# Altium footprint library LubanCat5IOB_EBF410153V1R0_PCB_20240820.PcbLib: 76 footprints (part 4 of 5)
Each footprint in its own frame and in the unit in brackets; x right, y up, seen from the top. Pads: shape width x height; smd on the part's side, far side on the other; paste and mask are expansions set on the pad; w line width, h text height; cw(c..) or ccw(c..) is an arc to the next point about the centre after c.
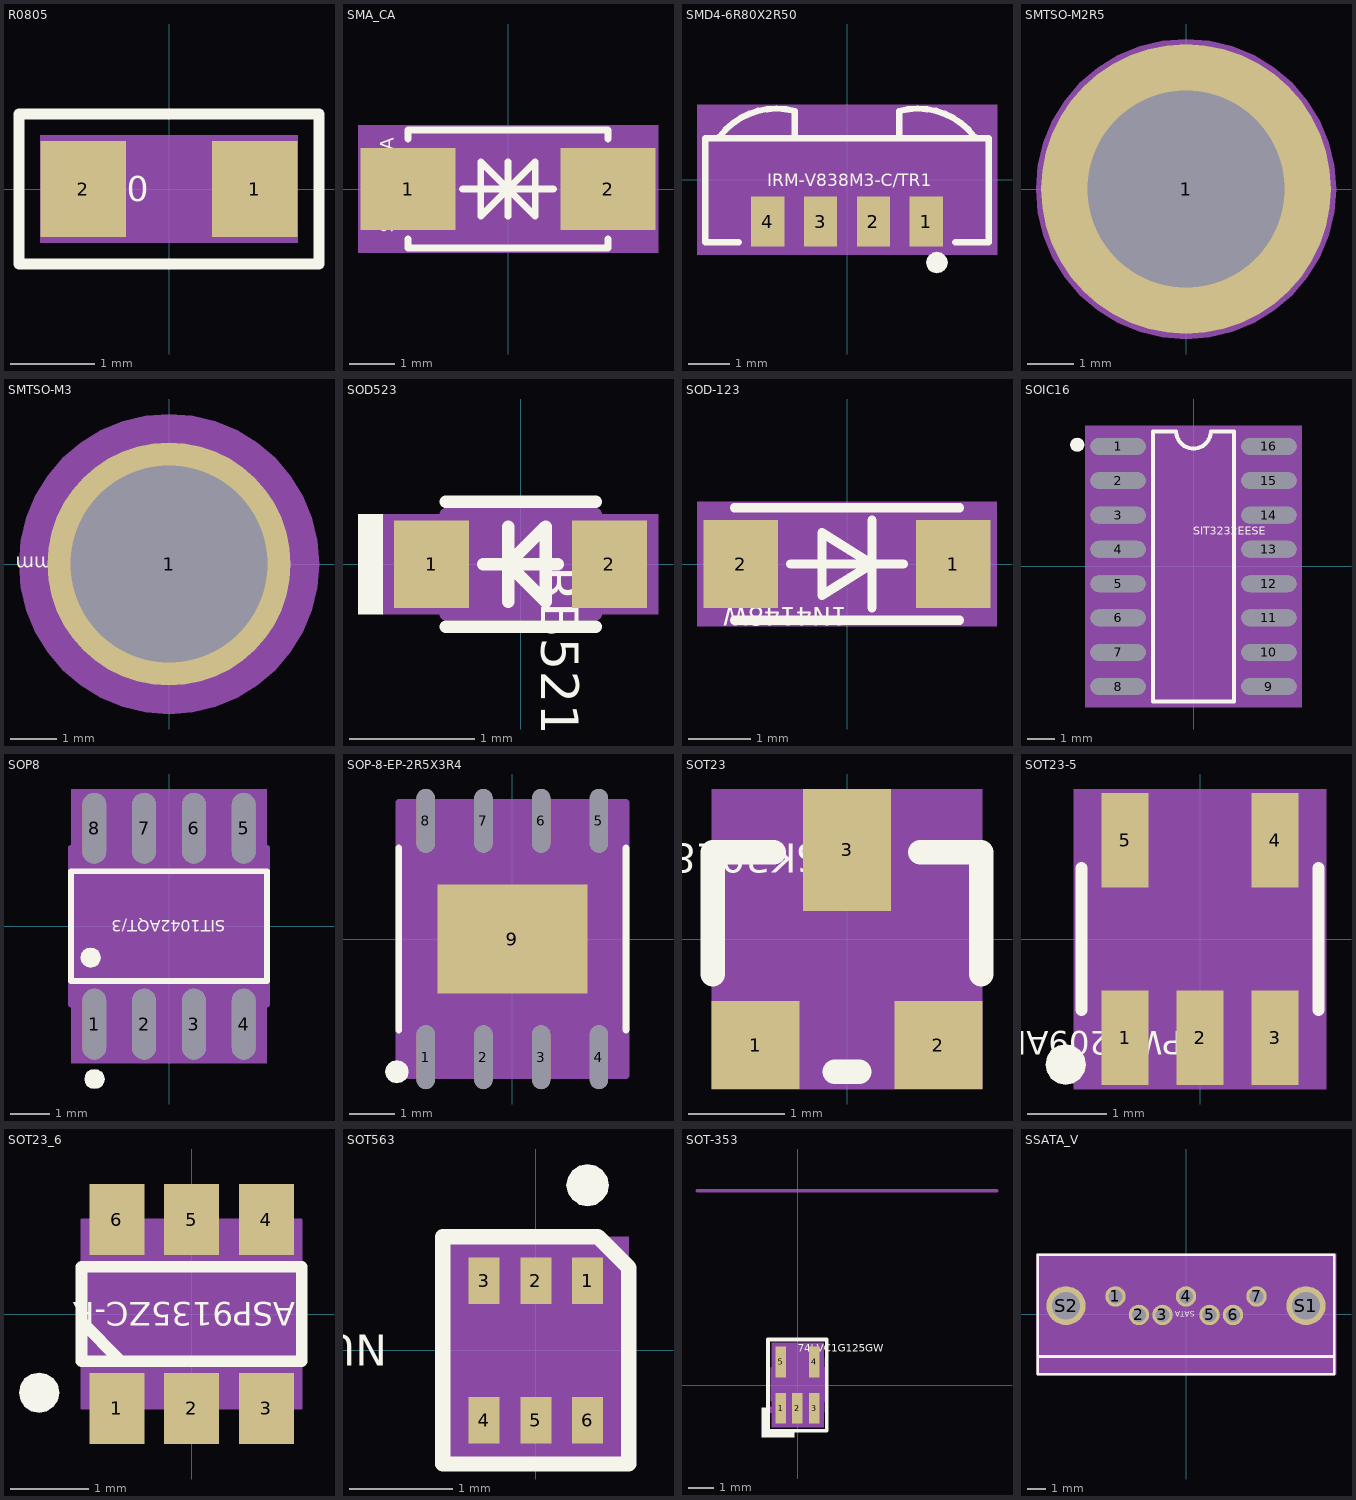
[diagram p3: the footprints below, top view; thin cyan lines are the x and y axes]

## R0805 [mil] "R0805"
pads (2):
  rect 40x45 smd: 1(40,0) 2(-40,0)
Top Overlay:
  lines w5: -70,-35 70,-35 70,35 -70,35 -70,-35
  text "0R" at -9.45,5.91 h11.81
Top 3D Body:
  region: 60,-25 -60,-25 -60,25 60,25
Mechanical 15:
  text "2" at -52,0 h30
  text "1" at 28,0 h30
3D body: height 150, standoff 0, extent -60,-25 60,25

## SMA_CA [mm] "SMA_CA"
pads (2):
  rect 2.1x1.8 smd: 1(-2.2,0) 2(2.2,0)
Top Overlay:
  lines w0.15: -2.2,-1.1 -2.2,-1.3 2.2,-1.3 2.2,-1.1 ; -2.2,1.1 -2.2,1.3 2.2,1.3 2.2,1.1 ; -1,0 1,0 ; 0,-0.6 0,0.6 ; 0,0 -0.6,-0.6 -0.6,0.6 0,0 ; 0,0 0.6,0.6 0.6,-0.6 0,0
  text "SMAJ13CA" at -2.517,-0.96 h0.3
Top 3D Body:
  region: -3.3,1.4 -3.3,-1.4 3.3,-1.4 3.3,1.4
Mechanical 15:
  text "2" at 2.2,-0.254 h0.64
  text "1" at -2.2,-0.254 h0.64
Top Assembly:
  lines w0.15: -2.2,-1.25 2.2,-1.25 2.2,1.25 -2.2,1.25 -2.2,-1.25
3D body: height 3.81, standoff 0, extent -3.3,-1.4 3.3,1.4

## SMD4-6R80X2R50 [mm] "SMD4-6R80X2R50"
pads (4):
  rect 0.8x1.2 smd: 1(1.905,-1) 2(0.635,-1) 3(-0.635,-1) 4(-1.905,-1)
Top Overlay:
  dashed: 2.414,-1.985 2.395,-1.887 2.339,-1.805 2.257,-1.75 2.159,-1.73 2.061,-1.75 2.034,-1.768 1.979,-1.805 1.923,-1.887 1.904,-1.985 1.923,-2.083 1.979,-2.165 2.034,-2.202 2.061,-2.221 2.159,-2.24 2.257,-2.221 2.339,-2.165 2.395,-2.083
  lines w0.15: -2.6,-1.5 -3.4,-1.5 -3.4,1 3.4,1 3.4,-1.5 2.6,-1.5
  lines w0.152: -3.053,1.041 cw(c-1.7,0.011) -1.25,1.651 -1.25,1 ; 1.25,1 1.25,1.651 cw(c1.7,0.012) 3.053,1.041
  text "IRM-V838M3-C/TR1" at -1.92,-0.15 h0.3
Top 3D Body:
  region: -3.6,1.8 -3.6,-1.8 3.6,-1.8 3.6,1.8
Mechanical 15:
  text "3" at -0.889,-1 h0.64
  text "1" at 1.651,-1 h0.64
  text "4" at -2.159,-1 h0.64
  text "2" at 0.381,-1 h0.64
Top Assembly:
  lines w0.15: -3.4,-1.5 3.4,-1.5 3.4,1 -3.4,1 -3.4,-1.5
3D body: height 3.81, standoff 0, extent -3.6,-1.8 3.6,1.8

## SMTSO-M2R5 [mm] "SMTSO-M2R5"
pads (1):
  round 6.2 / inner round 5.2 / far side round 5.2 hole 4.22: 1(0,0)
Top Overlay:
  text "M2.5X1.5mm" at -1.2,-0.15 h0.3
Top Paste:
  dashed: -0.4,3.074 -0.4,2.072 -0.579,2.029 -0.754,1.971 -0.923,1.898 -1.084,1.81 -1.238,1.709 -1.382,1.594 -1.516,1.468 -1.638,1.33 -1.748,1.182 -1.844,1.025 -1.926,0.861 -1.994,0.689 -2.047,0.513 -2.072,0.4 -3.074,0.4 -3.028,0.666 -2.958,0.928 -2.866,1.182 -2.752,1.427 -2.617,1.662 -2.462,1.883 -2.289,2.091 -2.098,2.282 -1.891,2.457 -1.67,2.612 -1.436,2.748 -1.191,2.862 -0.937,2.955 -0.676,3.026 -0.409,3.073
  dashed: -3.074,-0.4 -2.072,-0.4 -2.029,-0.579 -1.971,-0.754 -1.898,-0.923 -1.81,-1.084 -1.709,-1.238 -1.594,-1.382 -1.468,-1.516 -1.33,-1.638 -1.182,-1.748 -1.025,-1.844 -0.861,-1.926 -0.689,-1.994 -0.513,-2.047 -0.4,-2.072 -0.4,-3.074 -0.666,-3.028 -0.928,-2.958 -1.182,-2.866 -1.427,-2.752 -1.662,-2.617 -1.883,-2.462 -2.091,-2.289 -2.282,-2.098 -2.457,-1.891 -2.612,-1.67 -2.748,-1.436 -2.862,-1.191 -2.955,-0.937 -3.026,-0.676 -3.073,-0.409
  dashed: 0.4,-3.074 0.4,-2.072 0.579,-2.029 0.754,-1.971 0.923,-1.898 1.084,-1.81 1.238,-1.709 1.382,-1.594 1.516,-1.468 1.638,-1.33 1.748,-1.182 1.844,-1.025 1.926,-0.861 1.994,-0.689 2.047,-0.513 2.072,-0.4 3.074,-0.4 3.028,-0.666 2.958,-0.928 2.866,-1.182 2.752,-1.427 2.617,-1.662 2.462,-1.883 2.289,-2.091 2.098,-2.282 1.891,-2.457 1.67,-2.612 1.436,-2.748 1.191,-2.862 0.937,-2.955 0.676,-3.026 0.409,-3.073
  dashed: 3.074,0.4 2.072,0.4 2.029,0.579 1.971,0.754 1.898,0.923 1.81,1.084 1.709,1.238 1.594,1.382 1.468,1.516 1.33,1.638 1.182,1.748 1.025,1.844 0.861,1.926 0.689,1.994 0.513,2.047 0.4,2.072 0.4,3.074 0.666,3.028 0.928,2.958 1.182,2.866 1.427,2.752 1.662,2.617 1.883,2.462 2.091,2.289 2.282,2.098 2.457,1.891 2.612,1.67 2.748,1.436 2.862,1.191 2.955,0.937 3.026,0.676 3.073,0.409
Top 3D Body:
  region: 3.21,0 3.17,0.502 3.053,0.992 2.86,1.457 2.597,1.887 2.27,2.27 1.887,2.597 1.457,2.86 0.992,3.053 0.502,3.17 0,3.21 -0.502,3.17 -0.992,3.053 -1.457,2.86 -1.601,2.772 -1.887,2.597 -2.27,2.27 -2.597,1.887 -2.86,1.457 -3.053,0.992 -3.17,0.502 -3.21,0 -3.17,-0.502 -3.053,-0.992 -2.86,-1.457 -2.597,-1.887 -2.27,-2.27 -1.887,-2.597 -1.601,-2.772 -1.457,-2.86 -0.992,-3.053 -0.502,-3.17 0,-3.21 0.502,-3.17 0.992,-3.053 1.457,-2.86 1.887,-2.597 2.27,-2.27 2.597,-1.887 2.86,-1.457 3.053,-0.992 3.17,-0.502
Mechanical 15:
  text "1" at -0.254,0 h0.64
Top Assembly:
  circle w0.025: c0,0 r3.1
3D body: height 3.81, standoff 0, extent -3.21,-3.21 3.21,3.21

## SMTSO-M3 [mm] "SMTSO-M3"
pads (1):
  round 5.2 / inner round 5.2 / far side round 6.2 hole 4.22: 1(0,0)
Top Overlay:
  text "M3X3.5mm" at -0.96,0.15 h0.3
Top Paste:
  dashed: 3.074,-0.4 3.028,-0.666 2.958,-0.928 2.866,-1.182 2.752,-1.427 2.617,-1.662 2.462,-1.883 2.289,-2.091 2.098,-2.282 1.891,-2.457 1.67,-2.612 1.436,-2.748 1.191,-2.862 0.937,-2.955 0.676,-3.026 0.409,-3.073 0.4,-3.074 0.4,-2.062 0.578,-2.019 0.752,-1.961 0.92,-1.888 1.081,-1.8 1.234,-1.699 1.377,-1.585 1.51,-1.459 1.632,-1.322 1.741,-1.175 1.836,-1.019 1.918,-0.855 1.985,-0.684 2.037,-0.509 2.062,-0.4
  dashed: 0.4,3.074 0.666,3.028 0.928,2.958 1.182,2.866 1.427,2.752 1.662,2.617 1.883,2.462 2.091,2.289 2.282,2.098 2.457,1.891 2.612,1.67 2.748,1.436 2.862,1.191 2.955,0.937 3.026,0.676 3.073,0.409 3.074,0.4 2.062,0.4 2.019,0.578 1.961,0.752 1.888,0.92 1.8,1.081 1.699,1.234 1.585,1.377 1.459,1.51 1.322,1.632 1.175,1.741 1.019,1.836 0.855,1.918 0.684,1.985 0.509,2.037 0.4,2.062
  dashed: -3.074,0.4 -3.028,0.666 -2.958,0.928 -2.866,1.182 -2.752,1.427 -2.617,1.662 -2.462,1.883 -2.289,2.091 -2.098,2.282 -1.891,2.457 -1.67,2.612 -1.436,2.748 -1.191,2.862 -0.937,2.955 -0.676,3.026 -0.409,3.073 -0.4,3.074 -0.4,2.062 -0.578,2.019 -0.752,1.961 -0.92,1.888 -1.081,1.8 -1.234,1.699 -1.377,1.585 -1.51,1.459 -1.632,1.322 -1.741,1.175 -1.836,1.019 -1.918,0.855 -1.985,0.684 -2.037,0.509 -2.062,0.4
  dashed: -0.4,-3.074 -0.666,-3.028 -0.928,-2.958 -1.182,-2.866 -1.427,-2.752 -1.662,-2.617 -1.883,-2.462 -2.091,-2.289 -2.282,-2.098 -2.457,-1.891 -2.612,-1.67 -2.748,-1.436 -2.862,-1.191 -2.955,-0.937 -3.026,-0.676 -3.073,-0.409 -3.074,-0.4 -2.062,-0.4 -2.019,-0.578 -1.961,-0.752 -1.888,-0.92 -1.8,-1.081 -1.699,-1.234 -1.585,-1.377 -1.459,-1.51 -1.322,-1.632 -1.175,-1.741 -1.019,-1.836 -0.855,-1.918 -0.684,-1.985 -0.509,-2.037 -0.4,-2.062
Top 3D Body:
  region: 3.21,0 3.17,-0.502 3.053,-0.992 2.86,-1.457 2.597,-1.887 2.27,-2.27 1.887,-2.597 1.457,-2.86 0.992,-3.053 0.502,-3.17 0,-3.21 -0.502,-3.17 -0.992,-3.053 -1.457,-2.86 -1.601,-2.772 -1.887,-2.597 -2.27,-2.27 -2.597,-1.887 -2.86,-1.457 -3.053,-0.992 -3.17,-0.502 -3.21,0 -3.17,0.502 -3.053,0.992 -2.86,1.457 -2.597,1.887 -2.27,2.27 -1.887,2.597 -1.601,2.772 -1.457,2.86 -0.992,3.053 -0.502,3.17 0,3.21 0.502,3.17 0.992,3.053 1.457,2.86 1.887,2.597 2.27,2.27 2.597,1.887 2.86,1.457 3.053,0.992 3.17,0.502
Mechanical 15:
  text "1" at -0.376,0 h0.94
Top Assembly:
  circle w0.025: c0,0 r3.1
3D body: height 3.81, standoff 0, extent -3.21,-3.21 3.21,3.21

## SOD523 [mm] "SOD523"
pads (2):
  rect 0.6x0.7 smd: 1(-0.71,0) 2(0.71,0)
Top Overlay:
  dashed: -1.3,0.4 -1.3,-0.4 -1.1,-0.4 -1.1,0.4
  lines w0.1: -0.6,-0.5 0.6,-0.5 ; -0.6,0.5 0.6,0.5 ; -0.3,0 0.3,0 ; -0.1,-0.3 -0.1,0.3 ; -0.1,0 0.2,0.3 0.2,-0.3 -0.1,0
  text "RB521S-30" at 0.167,-0.016 h0.3
Top 3D Body:
  region: -1.1,0.4 -1.1,-0.4 1.1,-0.4 1.1,0.4
Mechanical 15:
  text "2" at 0.456,0 h0.64
  text "1" at -0.964,0 h0.64
Top Assembly:
  lines w0.1: -0.6,-0.4 0.6,-0.4 0.6,0.4 -0.6,0.4 -0.6,-0.4
3D body: height 3.81, standoff 0, extent -1.1,-0.4 1.1,0.4

## SOD-123 [mm] "SOD-123"
pads (2):
  rect 1.2x1.4 smd: 1(1.7,0) 2(-1.7,0)
Top Overlay:
  lines w0.15: -1.8,-0.9 1.8,-0.9 ; -1.8,0.9 1.8,0.9 ; -0.9,0 0.9,0 ; 0.4,-0.7 0.4,0.7 ; -0.4,-0.5 -0.4,0.5 0.4,0 -0.4,-0.5
  text "1N4148W" at 0,-0.69 h0.3
Top 3D Body:
  region: -2.4,-1 2.4,-1 2.4,1 -2.4,1
Mechanical 15:
  text "2" at -1.7,-0.315 h0.79
  text "1" at 1.7,-0.315 h0.79
Top Assembly:
  lines w0.15: -1.8,-0.9 1.8,-0.9 1.8,0.9 -1.8,0.9 -1.8,-0.9
3D body: height 3.81, standoff 0, extent -2.4,-1 2.4,1

## SOIC16 [mil] "SOIC16"
pads (16):
  oval 80x24 smd: 1(-109.8,174.8) 2(-109.8,125.2) 3(-109.8,74.8) 4(-109.8,25.2) 5(-109.8,-25.2) 6(-109.8,-74.8) 7(-109.8,-125.2) 8(-109.8,-174.8) 9(109.8,-174.8) 10(109.8,-125.2) 11(109.8,-74.8) 12(109.8,-25.2) 13(109.8,25.2) 14(109.8,74.8) 15(109.8,125.2) 16(109.8,174.8)
Top Overlay:
  dashed: -169.29,167.13 -165.45,167.89 -162.2,170.07 -160.02,173.32 -159.26,177.16 -160.02,181.01 -160.75,182.1 -162.2,184.26 -165.45,186.44 -169.29,187.2 -173.13,186.44 -176.39,184.26 -177.83,182.1 -178.56,181.01 -179.33,177.16 -178.56,173.32 -176.39,170.07 -173.13,167.89
  lines w5.91: -59.05,-196.85 -59.05,196.85 -39.37,196.85 -25.2,196.85 ccw(c0,196.85) 25.2,196.85 59.05,196.85 59.05,-196.85 -59.05,-196.85
  text "SIT3232EESE" at -0.01,46.06 h11.81
Top 3D Body:
  region: -157.48,204.72 -157.48,-204.72 157.48,-204.72 157.48,204.72
Mechanical 15:
  text "15" at 109.8,134.8 h12
  text "16" at 109.8,184.4 h12
  text "14" at 109.8,84.4 h12
  text "13" at 109.8,34.8 h12
  text "10" at 109.8,-115.6 h12
  text "8" at -109.8,-170 h12
  text "4" at -109.8,30 h12
  text "6" at -109.8,-70 h12
  text "9" at 109.8,-170 h12
  text "11" at 109.8,-65.2 h12
  text "1" at -109.8,179.6 h12
  text "7" at -109.8,-120.4 h12
  text "3" at -109.8,79.6 h12
  text "12" at 109.8,-15.6 h12
  text "2" at -109.8,130 h12
  text "5" at -109.8,-20.4 h12
3D body: height 150, standoff 0, extent -157.48,-204.72 157.48,204.72

## SOP8 [mm] "SOP8"
pads (8):
  oval 0.6x1.8 smd: 1(-1.905,-2.5) 2(-0.635,-2.5) 3(0.635,-2.5) 4(1.905,-2.5) 5(1.905,2.5) 6(0.635,2.5) 7(-0.635,2.5) 8(-1.905,2.5)
Top Overlay:
  dashed: -2.155,-3.9 -2.135,-3.998 -2.08,-4.08 -1.998,-4.135 -1.9,-4.155 -1.802,-4.135 -1.775,-4.117 -1.72,-4.08 -1.665,-3.998 -1.645,-3.9 -1.665,-3.802 -1.72,-3.72 -1.775,-3.683 -1.802,-3.665 -1.9,-3.645 -1.998,-3.665 -2.08,-3.72 -2.135,-3.802
  dashed: -2.255,-0.8 -2.235,-0.898 -2.18,-0.98 -2.098,-1.035 -2,-1.055 -1.902,-1.035 -1.875,-1.017 -1.82,-0.98 -1.765,-0.898 -1.745,-0.8 -1.765,-0.702 -1.82,-0.62 -1.875,-0.583 -1.902,-0.565 -2,-0.545 -2.098,-0.565 -2.18,-0.62 -2.235,-0.702
  lines w0.15: -2.5,-1.4 2.5,-1.4 2.5,1.4 -2.5,1.4 -2.5,-1.4
  text "SIT1042AQT/3" at 1.44,0.15 h0.3
Top 3D Body:
  region: -2.5,3.5 -2.5,-3.5 2.5,-3.5 2.5,3.5
Mechanical 15:
  text "4" at 2.159,-2.5 h0.64
  text "6" at 0.889,2.5 h0.64
  text "7" at -0.381,2.5 h0.64
  text "1" at -1.651,-2.5 h0.64
  text "8" at -1.651,2.5 h0.64
  text "2" at -0.381,-2.5 h0.64
  text "5" at 2.159,2.5 h0.64
  text "3" at 0.889,-2.5 h0.64
Top Assembly:
  lines w0.15: -2.5,-2 2.5,-2 2.5,2 -2.5,2 -2.5,-2
3D body: height 3.81, standoff 0, extent -2.5,-3.5 2.5,3.5

## SOP-8-EP-2R5X3R4 [mm] "SOP-8-EP-2R5X3R4"
pads (9):
  oval 0.4x1.4 smd: 1(-1.905,-2.6) 2(-0.635,-2.6) 3(0.635,-2.6) 4(1.905,-2.6) 5(1.905,2.6) 6(0.635,2.6) 7(-0.635,2.6) 8(-1.905,2.6)
  rect 3.3x2.4 smd: 9(0,0)
Top Overlay:
  dashed: -2.285,-2.921 -2.305,-2.823 -2.36,-2.741 -2.442,-2.686 -2.54,-2.666 -2.638,-2.686 -2.665,-2.704 -2.72,-2.741 -2.775,-2.823 -2.795,-2.921 -2.775,-3.019 -2.72,-3.101 -2.665,-3.138 -2.638,-3.156 -2.54,-3.176 -2.442,-3.156 -2.36,-3.101 -2.305,-3.019
  lines w0.15: -2.5,-2 -2.5,2 ; 2.5,-2 2.5,2
  text "NS4110B" at -0.84,-0.15 h0.3
Top 3D Body:
  region: -2.5,3 -2.5,-3 2.5,-3 2.5,3
Mechanical 15:
  text "9" at -0.254,0 h0.64
  text "7" at -0.889,2.6 h0.64
  text "2" at -0.889,-2.6 h0.64
  text "3" at 0.381,-2.6 h0.64
  text "1" at -2.159,-2.6 h0.64
  text "8" at -2.159,2.6 h0.64
  text "6" at 0.381,2.6 h0.64
  text "5" at 1.651,2.6 h0.64
  text "4" at 1.651,-2.6 h0.64
Top Assembly:
  lines w0.15: -2.5,-3 2.5,-3 2.5,3 -2.5,3 -2.5,-3
3D body: height 3.81, standoff 0, extent -2.5,-3 2.5,3

## SOT23 [mil] "SOT23"
pads (3):
  rect 36x36 smd: 1(-37.5,-43.5) 2(37.5,-43.5)
  rect 36x50 smd: 3(0,36.5)
Top Overlay:
  lines w10: -55,-14.5 -55,35.5 -30,35.5 ; -5,-54.5 5,-54.5 ; 30,35.5 55,35.5 55,-14.5
  text "2SK3018" at -0.01,38.98 h11.81
Top 3D Body:
  region: -55.5,-61.5 -55.5,61.5 55.5,61.5 55.5,-61.5
Mechanical 15:
  text "2" at 37.5,-25.5 h45
  text "3" at 0,54.5 h45
  text "1" at -37.5,-25.5 h45
3D body: height 150, standoff 0, extent -55.5,-61.5 55.5,61.5

## SOT23-5 [mm] "SOT23-5"
pads (5):
  rect 0.599x1.199 smd: 1(-0.95,-1.25) 2(0,-1.25) 3(0.95,-1.25) 4(0.95,1.25) 5(-0.95,1.25)
Top Overlay:
  dashed: -1.702,-1.336 -1.799,-1.355 -1.882,-1.411 -1.937,-1.493 -1.957,-1.591 -1.937,-1.688 -1.919,-1.716 -1.882,-1.771 -1.799,-1.826 -1.702,-1.846 -1.604,-1.826 -1.522,-1.771 -1.485,-1.716 -1.466,-1.688 -1.447,-1.591 -1.466,-1.493 -1.522,-1.411 -1.604,-1.355
  lines w0.15: -1.5,-0.9 -1.5,0.9 ; 1.5,-0.9 1.5,0.9
  text "LPW5209AB5F" at 0,-1.17 h0.3
Top 3D Body:
  region: -1.6,1.9 -1.6,-1.9 1.6,-1.9 1.6,1.9
Mechanical 15:
  text "5" at -0.95,1.21 h0.1
  text "2" at 0,-1.29 h0.1
  text "3" at 0.95,-1.29 h0.1
  text "4" at 0.95,1.21 h0.1
  text "1" at -0.95,-1.29 h0.1
Top Assembly:
  lines w0.15: -1.5,-0.85 1.5,-0.85 1.5,0.85 -1.5,0.85 -1.5,-0.85
3D body: height 3.81, standoff 0, extent -1.6,-1.9 1.6,1.9

## SOT23_6 [mm] "SOT23_6"
pads (6):
  rect 0.7x0.9 smd: 1(-0.95,-1.2) 2(0,-1.2) 3(0.95,-1.2) 4(0.95,1.2) 5(0,1.2) 6(-0.95,1.2)
Top Overlay:
  dashed: -2.195,-1 -2.176,-1.098 -2.12,-1.18 -2.038,-1.236 -1.94,-1.255 -1.842,-1.236 -1.815,-1.217 -1.76,-1.18 -1.704,-1.098 -1.685,-1 -1.704,-0.902 -1.76,-0.82 -1.815,-0.783 -1.842,-0.764 -1.94,-0.745 -2.038,-0.764 -2.12,-0.82 -2.176,-0.902
  lines w0.15: -1.4,-0.1 -0.9,-0.6 ; -1.4,-0.6 -1.4,0.6 1.4,0.6 1.4,-0.6 -1.4,-0.6
  text "ASP9135ZC-R" at 1.32,0.15 h0.3
Top 3D Body:
  region: -1.4,-1.2 1.4,-1.2 1.4,1.2 -1.4,1.2
Mechanical 15:
  text "3" at 1.204,-1.2 h0.64
  text "1" at -0.696,-1.2 h0.64
  text "4" at 1.204,1.2 h0.64
  text "5" at 0.254,1.2 h0.64
  text "2" at 0.254,-1.2 h0.64
  text "6" at -0.696,1.2 h0.64
Top Assembly:
  lines w0.025: -1.4,-1.2 1.4,-1.2 1.4,1.2 -1.4,1.2 -1.4,-1.2
3D body: height 3.81, standoff 0, extent -1.4,-1.2 1.4,1.2

## SOT563 [mm] "SOT563"
pads (6):
  rect 0.3x0.45 smd: 1(0.5,0.675) 2(0,0.675) 3(-0.5,0.675) 4(-0.5,-0.675) 5(0,-0.675) 6(0.5,-0.675)
Top Overlay:
  dashed: 0.704,1.6 0.688,1.522 0.644,1.456 0.578,1.412 0.5,1.396 0.422,1.412 0.4,1.426 0.356,1.456 0.312,1.522 0.296,1.6 0.312,1.678 0.356,1.744 0.4,1.774 0.422,1.788 0.5,1.804 0.578,1.788 0.644,1.744 0.688,1.678
  lines w0.15: -0.9,-1.1 0.8,-1.1 0.9,-1.1 0.9,0.8 0.6,1.1 -0.9,1.1 -0.9,-1.1
  text "NUP5120X6T1G" at -1.44,0.15 h0.3
Top 3D Body:
  region: 0.9,-1.1 0.9,1.1 -0.9,1.1 -0.9,-1.1
Mechanical 15:
  text "2" at -0.344,0.775 h0.3
  text "5" at -0.344,-0.575 h0.3
  text "6" at 0.156,-0.575 h0.3
  text "1" at 0.156,0.775 h0.3
  text "4" at -0.844,-0.575 h0.3
  text "3" at -0.844,0.775 h0.3
Top Assembly:
  lines w0.15: -0.75,-0.55 0.75,-0.55 0.75,0.55 -0.75,0.55 -0.75,-0.55
3D body: height 3.81, standoff 0, extent -0.9,-1.1 0.9,1.1

## SOT-353 [mil] "SOT-353"
pads (5):
  rect 16x47 smd: 1(-25.91,-35.43) 2(-0.32,-35.43) 3(25.28,-35.43) 4(25.28,35.43) 5(-25.91,35.43)
Top Overlay:
  dashed: -45.31,-35 -55.31,-35 -55.31,-80 -5.32,-80 -5.32,-70 -45.31,-70
  lines w6: -45.31,-70 44.69,-70 44.69,70 -45.31,70 -45.31,-70
  text "74LVC1G125GW" at -0.01,50.79 h11.81
  text ".Designator" at -0.01,8.27 h11.81
Mechanical 5:
  dashed: -39.69,-65 39.69,-65 39.69,65 -39.69,65
Top 3D Body:
  region: -39.69,-65 39.69,-65 39.69,65 -39.69,65
Top Component Center:
  circle w1: c-0.32,0 r11.81
  circle w1: c-0.32,0 r11.81
  lines w1: -16.06,0 15.43,0 -16.06,0 ; -0.32,-15.75 -0.32,15.75 -0.32,-15.75
Mechanical 15:
  text "5" at -25.91,42.23 h17
  text "3" at 25.28,-28.63 h17
  text "1" at -25.91,-28.63 h17
  text "2" at -0.32,-28.63 h17
  text "4" at 25.28,42.23 h17
Top Assembly:
  circle w3.94: c-41.31,-38 r2.83
  lines w3.94: -32.31,-24 -32.31,-40.83 -20.32,-40.83 ; -31.5,26 -31.5,40.83 ; -31.5,41.83 -19.5,41.83 -19.5,26 ; -20.32,-40 -20.32,-25 ; -6.32,-24 -6.32,-40.83 5.68,-40.83 ; 5.68,-40 5.68,-24 ; 19.68,-24 19.68,-40.83 31.68,-40.83 ; 19.68,26 19.68,41 ; 19.68,41.83 31.68,41.83 31.68,26 ; 31.68,-40 31.68,-24 ; -39.31,-23.61 40.69,-23.61 40.69,25.61 -39.31,25.61 -39.31,-23.61
Mechanical 18:
  lines w5: -154.31,298 305.69,298
  text "Remark: ***" at -124.31,98 h25
  text "Rev   : A1" at -124.31,138 h25
  text "Date  : 2007-11-30" at -124.31,178 h25
  text "Creat : Yuki" at -124.31,218 h25
  text "Ref PN: ESDALC6V1W5" at -124.31,258 h25
  text "Sofer Lib Information" at -154.31,308 h25
Mechanical 20:
  lines w1: -39.31,-41 40.69,-41 40.69,42 -39.31,42 -39.31,-41
Mechanical 21:
  text "Approved" at -0.32,112 h35
Mechanical 22:
  text "SOT-353" at 4.68,-79 h30
3D body: height 150, standoff 0, extent -39.69,-65 39.69,65

## SSATA_V [mm] "SSATA_V"
pads (9):
  round 1.1 hole 0.75: 1(-3.81,0.95) 4(0,0.95) 7(3.81,0.95)
  round 1.1 / inner round 1.524 / far side round 1.1 hole 0.75: 2(-2.54,-0.05) 3(-1.27,-0.05) 5(1.27,-0.05) 6(2.54,-0.05)
  round 2.1 hole 1.5: S1(6.48,0.45) S2(-6.48,0.45)
Top Overlay:
  lines w0.15: -8,-2.3 8,-2.3 ; -8,-3.25 8,-3.25 8,3.2 -8,3.2 -8,-3.25
  text "SATA" at 0.48,0.15 h0.3
Bottom Overlay:
  lines w0.3: -3.6,0.05 -2.8,0.85 ; -1,0.85 -0.2,0.05 0.2,0.05 1,0.85 ; 2.8,0.85 3.6,0.05
Top 3D Body:
  region: -8.1,3.25 -8.1,-3.25 8.1,-3.25 8.1,3.25
Mechanical 15:
  text "S1" at 6.3,0.25 h0.64
  text "S2" at -6.8,0.25 h0.64
  text "7" at 4.318,0.95 h0.64
  text "4" at 0.508,0.95 h0.64
  text "1" at -3.302,0.95 h0.64
  text "6" at 3.048,-0.05 h0.64
  text "5" at 1.778,-0.05 h0.64
  text "3" at -0.762,-0.05 h0.64
  text "2" at -2.032,-0.05 h0.64
Top Assembly:
  lines w0.15: -8,3.2 8,3.2 8,-2.3 ; -8,3.2 -8,-2.3 8,-2.3 ; -8,3.2 -8,-3.25 8,-3.25 8,-2.3 ; -8,-1.55 8,-1.55 8,2.45 -8,2.45 -8,-1.55
3D body: height 3.81, standoff 0, extent -8.1,-3.25 8.1,3.25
